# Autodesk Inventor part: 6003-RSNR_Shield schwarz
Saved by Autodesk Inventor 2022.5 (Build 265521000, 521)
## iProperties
Created: 2024-12
Part Number: 6003-RSNR_Shield schwarz
Material: Generic
Document SubType Name: Modeling
Designer: AdminForWorker
Density: 1 g/cm^3
Appearance: Default
Title: 6003-RSNR_Shield schwarz
Author: AdminForWorker
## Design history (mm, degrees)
feature "Body1"
body "Solid1"
